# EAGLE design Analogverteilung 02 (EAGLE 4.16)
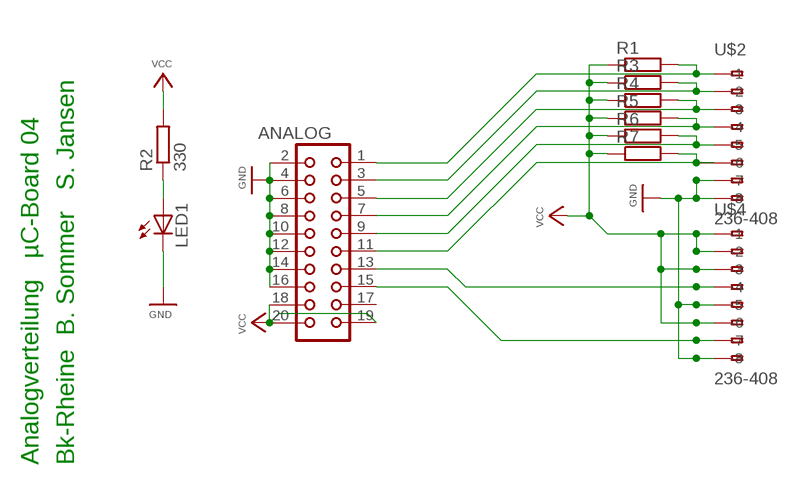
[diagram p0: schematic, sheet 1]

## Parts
ANALOG  CON20  [CON20]
LED1  LED3MM  [LED3MM]
R1  R-EU_0207/12  [0207/12]
R2  330  R-EU_0207/10  [0207/10]
R3  R-EU_0207/12  [0207/12]
R4  R-EU_0207/12  [0207/12]
R5  R-EU_0207/12  [0207/12]
R6  R-EU_0207/12  [0207/12]
R7  R-EU_0207/12  [0207/12]
U$2  236-408  [236-408]
U$4  236-408  [236-408]

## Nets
GND: ANALOG.2 ANALOG.4 ANALOG.6 ANALOG.8 ANALOG.10 ANALOG.12 ANALOG.14 ANALOG.16 LED1.K(C) U$2.A7(-7) U$2.A8(-8) U$2.B7(B-7) U$2.B8(B-8) U$4.A5(-5) U$4.A8(-8) U$4.B5(B-5) U$4.B8(B-8)
N$2: LED1.A R2.1
PA0: ANALOG.15 U$4.A7(-7) U$4.B7(B-7)
PA1: ANALOG.13 U$4.A4(-4) U$4.B4(B-4)
PA2: ANALOG.11 R7.2 U$2.A6(-6) U$2.B6(B-6)
PA3: ANALOG.9 R6.2 U$2.A5(-5) U$2.B5(B-5)
PA4: ANALOG.7 R5.2 U$2.A4(-4) U$2.B4(B-4)
PA5: ANALOG.5 R4.2 U$2.A3(-3) U$2.B3(B-3)
PA6: ANALOG.3 R3.2 U$2.A2(-2) U$2.B2(B-2)
PA7: ANALOG.1 R1.2 U$2.A1(-1) U$2.B1(B-1)
VCC: ANALOG.18 ANALOG.19 ANALOG.20 R1.1 R2.2 R3.1 R4.1 R5.1 R6.1 R7.1 U$4.A1(-1) U$4.A2(-2) U$4.A3(-3) U$4.A6(-6) U$4.B1(B-1) U$4.B2(B-2) U$4.B3(B-3) U$4.B6(B-6)
Unconnected: ANALOG.17

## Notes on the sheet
- Analogverteilung   µC-Board 04 | Bk-Rheine  B. Sommer   S. Jansen

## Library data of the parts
ANALOG = con-harting:CON20: CONNECTOR
LED1 = led:LED: LED
R1-R7 = rcl:R-EU_: RESISTOR, European symbol
U$2 U$4 = con-wago255:236-408

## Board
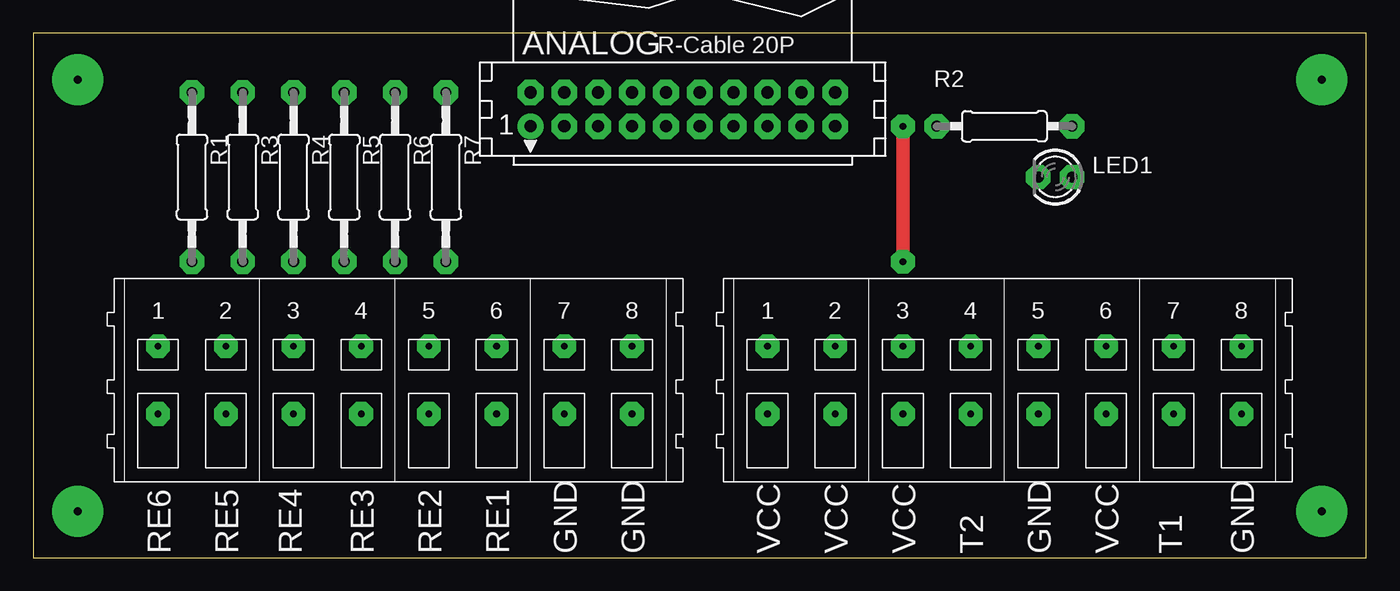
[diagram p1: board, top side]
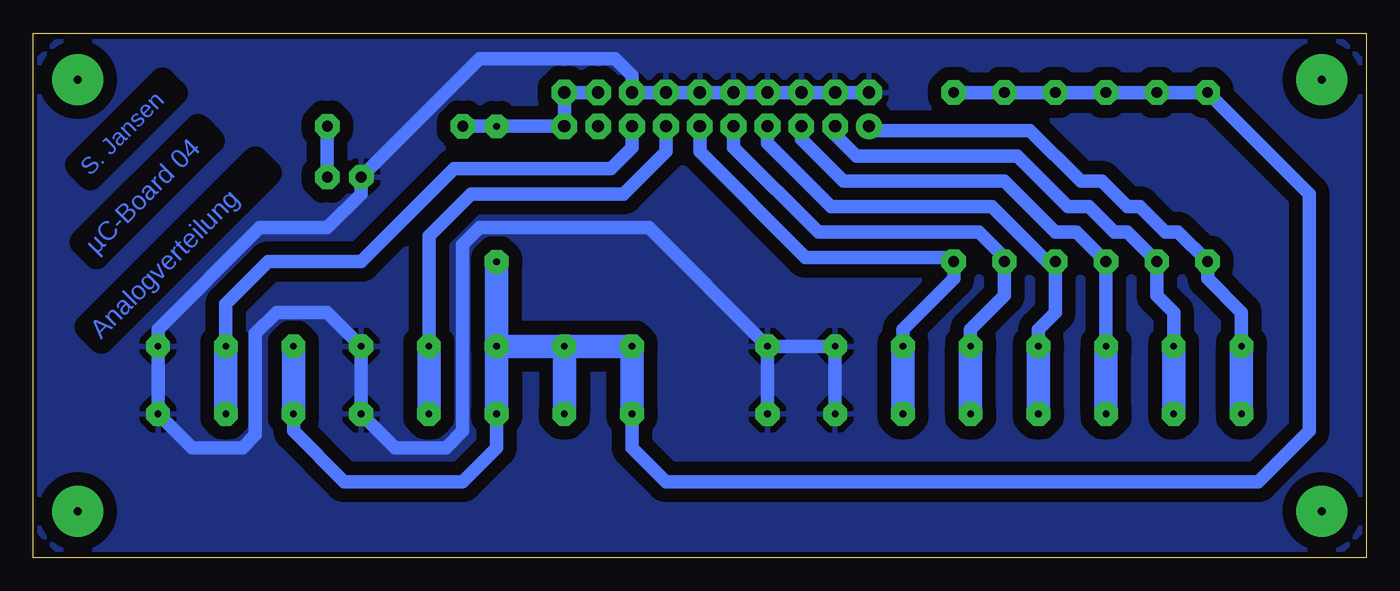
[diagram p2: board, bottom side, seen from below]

Size 100 x 39.36 mm. Coordinates in mm from the lower left corner, seen from the top.
Outline: 0,0 100,0 100,39.36 0,39.36 0,0
Copper layers (1*16): Top 0.035mm / dielectric 1.5mm / Bottom 0.035mm
Design rules "Ätzen_Schule": minimum track width 24mil, minimum drill 0.5mm, track to track 20mil, track to pad 24mil, pad to pad 24mil, via to via 24mil, smd to smd 8mil, copper to edge 0mil, drill to drill 8mil, minimum pad ring 20mil, minimum via ring 20mil, stop-mask expansion 4mil, vias tented up to drill 0mil, thermal gap 20mil

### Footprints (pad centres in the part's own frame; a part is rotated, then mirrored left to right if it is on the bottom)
CON20 = drill 0.914 round: 1 -11.43,-1.27 | drill 0.914 octagon: 2 -11.43,1.27; 3 -8.89,-1.27; 4 -8.89,1.27; 5 -6.35,-1.27; 6 -6.35,1.27; 7 -3.81,-1.27; 8 -3.81,1.27; 9 -1.27,-1.27; 10 -1.27,1.27; 11 1.27,-1.27; 12 1.27,1.27; 13 3.81,-1.27; 14 3.81,1.27; 15 6.35,-1.27; 16 6.35,1.27; 17 8.89,-1.27; 18 8.89,1.27; 19 11.43,-1.27; 20 11.43,1.27
LED3MM = drill 0.813 octagon: A -1.27,0; K 1.27,0
0207/12 = drill 0.813 octagon: 1 -6.35,0; 2 6.35,0
0207/10 = drill 0.813 octagon: 1 -5.08,0; 2 5.08,0
236-408 = drill 0.5 pad 1.778 octagon: A1 -17.78,2.54; A2 -12.7,2.54; A3 -7.62,2.54; A4 -2.54,2.54; A5 2.54,2.54; A6 7.62,2.54; A7 12.7,2.54; A8 17.78,2.54; B1 -17.78,-2.54; B2 -12.7,-2.54; B3 -7.62,-2.54; B4 -2.54,-2.54; B5 2.54,-2.54; B6 7.62,-2.54; B7 12.7,-2.54; B8 17.78,-2.54

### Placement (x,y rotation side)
ANALOG  48.73,33.65 0 top
LED1  76.67,28.57 180 top
R1  11.9,28.57 270 top
R2  72.86,32.38 180 top
R3  15.71,28.57 270 top
R4  19.52,28.57 270 top
R5  23.33,28.57 270 top
R6  27.14,28.57 270 top
R7  30.95,28.57 270 top
U$2  27.14,13.33 0 top
U$4  72.86,13.33 0 top

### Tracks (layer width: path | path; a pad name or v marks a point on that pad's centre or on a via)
GND
  Bottom 1.016: ANALOG.2 ANALOG.4 ANALOG.6 ANALOG.8 ANALOG.10 ANALOG.12 ANALOG.14 ANALOG.16 55.08,36.19 56.35,37.46 66.51,37.46 LED1.K 75.4,27.3 77.94,24.76 83.02,24.76 90.64,17.14 U$4.A8 U$4.B8 88.1,8.25 84.29,8.25 83.34,9.2 83.34,16.82 81.75,18.41 77.94,18.41 U$4.A5 U$4.B5 72.86,8.25 69.05,8.25 67.78,9.52 67.78,23.49 66.51,24.76 53.81,24.76 U$2.A8 | U$2.A8 U$2.B8 | U$2.B7 U$2.A7 U$2.A8
  pour Bottom (isolate 1.016): 98.26,38.73 99.53,37.46 99.53,1.9 98.26,0.63 1.74,0.63 0.47,1.9 0.47,37.46 1.74,38.73
N$1
  pour Bottom (isolate 1.016): 1.74,38.73 98.26,38.73 99.53,37.46 99.53,1.9 98.26,0.63 1.74,0.63 0.47,1.9 0.47,37.46
N$2
  Bottom 1.016: LED1.A R2.1
N$3  (via drill 0.6 pad 3.81)
  other vias: 3.33,35.87
N$4  (via drill 0.6 pad 3.81)
  other vias: 96.67,35.87
N$5  (via drill 0.6 pad 3.81)
  other vias: 96.67,3.49
N$6  (via drill 0.6 pad 3.81)
  other vias: 3.33,3.49
PA0
  Bottom 1.016: ANALOG.15 55.08,30.79 56.67,29.2 68.41,29.2 75.4,22.22 82.39,22.22 85.56,19.04 U$4.A7
  Bottom 1.778: U$4.A7 U$4.B7
PA1
  Bottom 1.016: ANALOG.13 52.54,30.47 55.71,27.3 67.14,27.3 70.32,24.12 U$4.A4
  Bottom 1.778: U$4.B4 U$4.A4
PA2
  Bottom 1.016: ANALOG.11 50,30.47 42.06,22.54 33.81,22.54 | 33.81,22.54 33.49,22.54 | 33.81,22.54 31.27,22.54 R7.2 31.27,22.22 30.95,21.9 30.95,20.95 34.76,17.14 U$2.A6
  Bottom 1.778: U$2.B6 U$2.A6
PA3
  Bottom 1.016: ANALOG.9 47.46,30.79 41.11,24.44 29.04,24.44 27.14,22.54 R6.2 27.14,19.68 29.68,17.14 U$2.A5
  Bottom 1.778: U$2.B5 U$2.A5
PA4
  Bottom 1.016: ANALOG.7 44.92,31.11 40.16,26.35 28.09,26.35 23.96,22.22 R5.2 23.33,18.41 24.6,17.14 U$2.A4
  Bottom 1.778: U$2.B4 U$2.A4
PA5
  Bottom 1.016: ANALOG.5 42.38,31.43 39.2,28.25 27.14,28.25 23.33,24.44 21.74,24.44 R4.2 U$2.A3
  Bottom 1.778: U$2.B3 U$2.A3
PA6
  Bottom 1.016: ANALOG.3 39.84,31.74 38.25,30.16 26.19,30.16 22.38,26.35 20.79,26.35 18.88,24.44 17.93,24.44 R3.2 15.71,19.68 14.44,18.41 U$2.A2
  Bottom 1.778: U$2.B2 U$2.A2
PA7
  Bottom 1.016: ANALOG.1 36.98,32.06 25.23,32.06 21.42,28.25 19.84,28.25 17.93,26.35 16.98,26.35 15.08,24.44 14.12,24.44 R1.2 11.9,20.95 9.36,18.41 U$2.A1
  Bottom 1.778: U$2.B1 U$2.A1
VCC  (via drill 0.5 pad 1.78)
  Top 1.016: v65.24,22.22 v65.24,32.38
  Bottom 1.016: ANALOG.18 ANALOG.20 ANALOG.19 v65.24,32.38 R2.2 | R1.1 R3.1 | R3.1 R4.1 | R4.1 R5.1 | R5.1 R6.1 | R6.1 R7.1 R6.1 | R1.1 4.28,27.3 4.28,9.52 8.09,5.71 52.54,5.71 55.08,8.25 U$4.B1 | R5.1 R6.1 | R4.1 R5.1 | R1.1 R3.1 | U$4.B3 65.24,8.25 67.78,5.71 76.67,5.71 80.48,9.52 U$4.B6
  Bottom 1.778: U$4.B1 U$4.A1 U$4.A2 | U$4.A2 U$4.B2 | U$4.A3 U$4.B3 | U$4.B6 U$4.A6 | U$4.A3 v65.24,22.22 | U$4.A2 U$4.A3

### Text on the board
Bottom: S. Jansen | µC-Board 04 | Analogverteilung
tPlace: RE6 | RE5 | RE4 | RE3 | RE2 | RE1 | GND | GND | VCC | VCC | VCC | T2 | GND | VCC | T1 | GND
